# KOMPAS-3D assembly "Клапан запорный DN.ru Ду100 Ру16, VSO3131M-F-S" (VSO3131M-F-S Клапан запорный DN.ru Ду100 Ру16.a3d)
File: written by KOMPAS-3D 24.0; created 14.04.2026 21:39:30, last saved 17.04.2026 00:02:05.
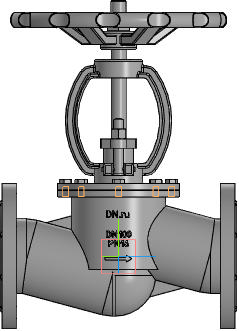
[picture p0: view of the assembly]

Document properties: Автор: R2D2; Полное имя файла: E:\Работа\Зайцев\VSO3131M-F-S Клапан запорный DN.ru Ду15-100 Ру16\DN100\исходные материалы\VSO3131M-F-S Клапан запорный DN.ru Ду100 Ру16.a3d

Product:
- Component [detail]: Корпус  | qty 1  | pos. 1  | Масса: 6.9; Автор: R2D2; source file: Корпус.m3d
- Component [detail]: Клапан запорный DN.ru Ду100 Ру16  | designation VSO1121M-F-S  | qty 1  | pos. 2  | Масса: 38.27; Раздел спецификации: Прочие изделия; Примечание: D090-01950; Автор: R2D2; source file: 2.m3d
- Part/product: Клапан запорный DN.ru Ду100 Ру16  | designation VSO3131M-F-S
    Масса: 26
    Раздел спецификации: Прочие изделия
    Примечание: D090-02954

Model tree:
1. Контекстная связь:2  (with: Ребро.Операция без истории:1, Контекстная связь (Корпус):2)
2. Контекстная связь:3  (with: Грань.Операция без истории:1, Контекстная связь (Корпус):3)
     Расстояние = -360

Referenced files in C:\Program Files\ASCON\KOMPAS-3D v24\Libs\Pipeline\: StylesTemplate.a3d, TemplateHPH, InsulationStylesTemplate.a3d, Insulation
Referenced files in C:\Program Files\ASCON\KOMPAS-3D v24\Templates\: Констр. чертеж А3 гориз. перв. лист.cdt
Referenced files in E:\Работа\Зайцев\VSO3131M-F-S Клапан запорный DN.ru Ду15-100 Ру16\DN100\исходные материалы\: , Корпус.m3d, 2.m3d
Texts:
  Отводы ГОСТ 17375-2001
  Констр. чертеж А3 гориз. перв. лист.cdt
  VSO3131M-F-S
  VSO1121M-F-S Клапан запорный DN.ru Ду100 Ру16
  Ось Y.Начало координат
  Плоскость ZY.Начало координат
  Плоскость ZX.Начало координат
